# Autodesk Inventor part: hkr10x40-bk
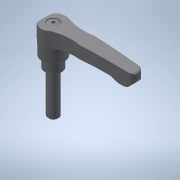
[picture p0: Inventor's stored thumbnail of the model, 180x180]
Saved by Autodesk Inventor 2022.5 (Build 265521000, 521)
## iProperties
Created: 2017-09
Part Number: hkr10x40-bk
Material: 一般
Document SubType Name: Modeling
Designer: imaocorp
Density: 1 g/cm^3
Appearance: 既定
Author: imaocorp
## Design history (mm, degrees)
node "hkr10x40-bk.x_t1"
node "hkr10x40-bk"
node "Base1"
